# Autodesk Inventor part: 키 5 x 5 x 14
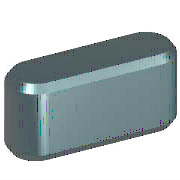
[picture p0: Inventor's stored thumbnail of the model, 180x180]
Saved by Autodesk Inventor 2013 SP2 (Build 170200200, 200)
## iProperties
IsCustomPart: 1
Created: 2012-02
Part Number: 키 5 x 5 x 14
Material: 강철, 연강
Description: 키 및 해당 키홈
Document SubType Name: Modeling
Standard: KS B 1311
Designer: mduedu
Standards Organization: KS
Language: ko-KR
Size Designation: 5 x 5 x 14
Categories: <MemberInstance><Categories><Category DisplayName="샤프트 부품" InternalName="7f7aeb1f-a693-4053-b835-cee3144e0d98" Mnemonic="SHFT"><Category DisplayName="키" Interna
Density: 1 g/cm^3
Author: mduedu
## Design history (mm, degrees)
workplane "Work Plane1"
workplane "Work Plane2"
sketch "스케치1"
  geometry: L1 (2.5, 2.5)-(11.5, 2.5); L2 (11.5, -2.5)-(2.5, -2.5); L3 (0, 9.4)-(0, -7.4) reference; L4 (-5, 0)-(30, 0) reference; L5 (14, 0)-(14, 7); A1 r 2.5 centre (2.5, 0) between (2.5, 2.5) and (2.5, -2.5); A2 r 2.5 centre (11.5, 0) between (11.5, -2.5) and (11.5, 2.5)
  constraints: 6 end point, 5 point on circle, 4 tangent, 3 point on line, 2 centre point, 1 horizontal, 1 parallel, 1 perpendicular
  dimensions: "d0" = 2.5 radius of A1 (= 0.5 x PB); "d13" = 2.5 radius of A2 (= 0.5 x PB); "d14" = 14 distance between parallel lines of L5 L3 (= NLG)
extrude "본체1" new body sketch "스케치1" taper "d3" = 0 deg; stored distance "d4" = 10
workplane "Work Plane3"
body "Solid1"
chamfer "모따기1" distance "d8" = 0.4 (= PHH); stored, may be unused: second distance "d9" = 0.4 (= PHH), angle "d15" = 45 deg
other parameters: "d1" = -3 (= -PNT), "d2" = 2 (= PH - PNT), "NLG" = 14 [user parameter; used in 3 equation terms], "PB" = 5 [user parameter; used in 2 equation terms], "PNT" = 3 [user parameter; used in 2 equation terms], "PH" = 5 [user parameter; used in 1 equation term], "PHH" = 0.4 [user parameter; used in 2 equation terms], "d10" = 0, "d16" = 0, "d17" = 0, "d18" = 0, "WDMIN" = 12 [user parameter], "PLB2" = 14 (= NLG) [user parameter], "WDMAX" = 17 [user parameter], "PLB1" = 14 (= NLG) [user parameter], "RR" = 0.16 [user parameter], "PUEB" = 2.3 [user parameter]
